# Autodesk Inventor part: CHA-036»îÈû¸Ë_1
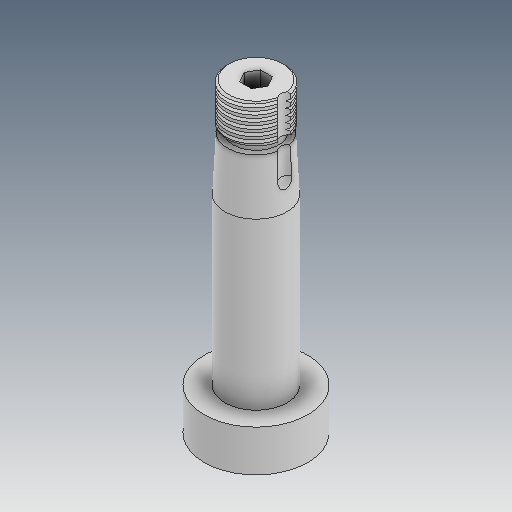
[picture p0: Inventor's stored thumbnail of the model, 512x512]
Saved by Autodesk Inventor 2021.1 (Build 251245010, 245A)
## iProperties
Created: 2019-12
Part Number: CHA-036»îÈû¸Ë_1
Material: Ogólny
Document SubType Name: Modeling
Designer: user
Density: 1 g/cm^3
Appearance: Domyślna
Author: user
Revision Number: ÈÎºÎ
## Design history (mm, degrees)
feature "ÊäÈë1"
node "Bryła1"
